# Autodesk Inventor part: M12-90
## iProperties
Created: 2006-02
Material: Steel, Mild
Description: ISO metric hexagon commercial bolts and screws
Document SubType Name: Modeling
Standard: AS 1111
Designer: Administrator
Standards Organization: AS
Language: en-US
Categories: <MemberInstance><Categories><Category DisplayName="Fasteners" InternalName="e4da775c-781d-43d5-af7c-5136215cf5a6" Mnemonic="FSTN"><Category DisplayName="Bolts"
Density: 1 g/cm^3
Author: Administrator
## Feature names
1. Body [Revolution]
2. Head [Extrusion]
3. Chamfer1 [Revolution]
4. Chamfer2
